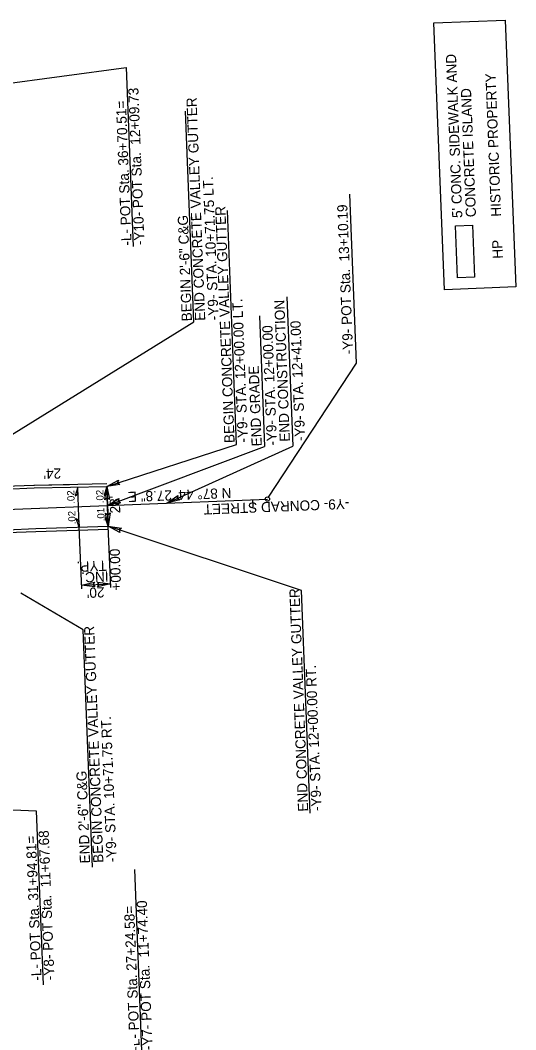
# Model space of a CAD drawing. Extents: x 1627861 to 1629601, y 761281 to 766239.
# Drawn here: x 1628556 to 1628898, y 763512 to 764207 of the extents above; entities that cross this region are included whole.
import ezdxf

# ---------------------------------------------------------------- set-up
doc = ezdxf.new("R2010")
doc.units = 0
for name, color, linetype in [('Cogo Default Point CELL', 7, 'Continuous'), ('Exist Other Culture Sign Leader', 7, 'Continuous'), ('Exist Property Tie Line Text', 7, 'Continuous'), ('Exist Right of Way Line Leader', 7, 'Continuous'), ('Exist Right of Way Monument Text', 7, 'Continuous'), ('Exist Utilities Gas Meter CELL', 7, 'Continuous'), ('Exist Utilities Gas Meter Cogo Number', 7, 'Continuous'), ('Exist Utilities Power UG Cable SUE LOS B Cogo Point CELL', 7, 'Continuous'), ('Exist Utilities Telephone UG Cable SUE LOS B Cogo Point CELL', 7, 'Continuous'), ('Exist Utilities Water UG Line SUE LOS B Cogo Number', 7, 'Continuous'), ('Exist Utilities Water Valve CELL', 7, 'Continuous'), ('Scratch_Level_0', 7, 'Continuous'), ('Typical Terminator CELL', 7, 'Continuous')]:
    doc.layers.add(name, color=color, linetype=linetype)

msp = doc.modelspace()

# ---------------------------------------------------------------- linework, layer by layer
at = {"layer": 'Exist Other Culture Sign Leader'}
msp.add_lwpolyline([(1628848.56, 764021.31), (1628841.32, 764205.02), (1628890.44, 764206.95), (1628897.68, 764023.24)], close=True, dxfattribs=at)
at = {"layer": 'Exist Property Tie Line Text'}
for p, q in [((1628616.55, 763872.84), (1628616.75, 763867.84)), ((1628716.48, 763876.78), (1628716.67, 763871.78))]:
    msp.add_line(p, q, dxfattribs=at)
at = {"layer": 'Exist Right of Way Line Leader'}
for p, q in [((1628407.18, 764144.24), (1628629.31, 764174.43)), ((1628629.31, 764174.43), (1628634.17, 764051.21)), ((1628787.95, 763970.8), (1628783.36, 764087.08)), ((1628727.48, 763878.43), (1628787.95, 763970.8)), ((1628425.93, 763668.97), (1628567.57, 763662.49)), ((1628567.57, 763662.49), (1628572.3, 763542.59)), ((1628640.24, 763497.24), (1628635.31, 763622.14))]:
    msp.add_line(p, q, dxfattribs=at)
msp.add_circle((1628726.66, 763877.18), 1.5, dxfattribs=at)
at = {"layer": 'Exist Right of Way Monument Text'}
for p, q in [((1628566.04, 763884.85), (1628616.04, 763885.81)), ((1628546.06, 763884.07), (1628566.04, 763884.85)), ((1628567.14, 763856.88), (1628617.12, 763858.53)), ((1628547.16, 763856.09), (1628567.14, 763856.88))]:
    msp.add_line(p, q, dxfattribs=at)
at = {"layer": 'Exist Utilities Gas Meter CELL'}
msp.add_line((1628416.71, 763864.95), (1628726.66, 763877.18), dxfattribs=at)
msp.add_line((1628416.71, 763864.95), (1628726.66, 763877.18), dxfattribs=at)
at = {"layer": 'Exist Utilities Gas Meter Cogo Number'}
for points in [[(1628614.85, 763876.75), (1628616.04, 763885.81), (1628618, 763876.83), (1628616.35, 763877.91)], [(1628625.08, 763887.1), (1628616.04, 763885.81), (1628624.16, 763890.11), (1628623.56, 763888.24)], [(1628666.36, 763876.75), (1628657.52, 763874.45), (1628665.11, 763879.64), (1628664.72, 763877.71)], [(1628625.52, 763874.54), (1628616.55, 763872.84), (1628624.47, 763877.51), (1628623.95, 763875.61)], [(1628618.31, 763867.59), (1628617.12, 763858.53), (1628615.16, 763867.51), (1628616.81, 763866.42)], [(1628625.17, 763854.21), (1628617.12, 763858.53), (1628626.21, 763857.19), (1628624.61, 763856.03)], [(1628607.76, 763816.75), (1628598.7, 763817.94), (1628607.68, 763819.9), (1628606.6, 763818.25)], [(1628609.63, 763819.92), (1628618.69, 763818.73), (1628609.71, 763816.77), (1628610.79, 763818.42)]]:
    msp.add_lwpolyline(points, close=True, dxfattribs=at)
at = {"layer": 'Exist Utilities Telephone UG Cable SUE LOS B Cogo Point CELL'}
for p, q in [((1628545.98, 763886.06), (1628565.96, 763886.85)), ((1628566, 763886.85), (1628616, 763887.81)), ((1628547.24, 763854.09), (1628567.22, 763854.88)), ((1628567.21, 763854.88), (1628617.18, 763856.53))]:
    msp.add_line(p, q, dxfattribs=at)
at = {"layer": 'Exist Utilities Water UG Line SUE LOS B Cogo Number'}
for p, q in [((1628597.13, 763857.87), (1628596.04, 763885.43)), ((1628617.12, 763858.53), (1628616.04, 763885.81))]:
    msp.add_line(p, q, dxfattribs=at)
at = {"layer": 'Exist Utilities Water Valve CELL'}
msp.add_lwpolyline([(1628857.58, 764029.59), (1628856.17, 764065.33), (1628867.81, 764065.79), (1628869.22, 764030.05)], close=True, dxfattribs=at)
at = {"layer": 'Scratch_Level_0'}
for p, q in [((1628675.94, 763999.17), (1628670.22, 764144.29)), ((1628705.44, 763914.68), (1628699.08, 764076)), ((1628740.15, 764016.47), (1628744.2, 763913.69)), ((1628721.18, 764003.45), (1628724.73, 763913.41)), ((1628487.81, 763882.77), (1628675.94, 763999.17)), ((1628616.04, 763885.81), (1628705.44, 763914.68)), ((1628616.55, 763872.84), (1628724.73, 763913.41)), ((1628657.52, 763874.45), (1628744.2, 763913.69)), ((1628566.41, 763886.81), (1628590.4, 763887.31)), ((1628616.04, 763885.81), (1628617.12, 763858.53)), ((1628598.8, 763815.44), (1628597.13, 763857.87)), ((1628618.79, 763816.22), (1628617.12, 763858.53)), ((1628750.05, 763814.21), (1628617.12, 763858.53)), ((1628598.7, 763817.94), (1628618.69, 763818.73)), ((1628599.89, 763787.01), (1628557.01, 763812.44)), ((1628756.09, 763660.87), (1628750.05, 763814.21)), ((1628606.33, 763623.75), (1628599.89, 763787.01))]:
    msp.add_line(p, q, dxfattribs=at)
at = {"layer": 'Typical Terminator CELL'}
for points in [[(1628596.04, 763885.43), (1628594.28, 763879.35), (1628596.22, 763880.8)], [(1628616.04, 763885.81), (1628614.28, 763879.73), (1628616.22, 763881.19)], [(1628617.12, 763858.53), (1628614.88, 763864.45), (1628616.94, 763863.15)], [(1628597.13, 763857.87), (1628594.89, 763863.79), (1628596.95, 763862.49)]]:
    msp.add_lwpolyline(points, close=True, dxfattribs=at)

# ---------------------------------------------------------------- texts
at = {"layer": 'Cogo Default Point CELL'}
msp.add_text('N 87%%d 44\' 27.8" E', height=7, rotation=182.25895, dxfattribs=at).set_placement((1628701.73, 763884.89))
at = {"layer": 'Exist Other Culture Sign Leader'}
for s, rotation, p in [("5' CONC. SIDEWALK AND", 92.25819, (1628860.94, 764070.86)), ('HISTORIC PROPERTY', 92.25819, (1628887.6, 764071.76)), ('CONCRETE ISLAND', 92.25819, (1628870.33, 764071.41)), ('HP', 92.25819, (1628888.8, 764042.83)), ('END CONSTRUCTION', 92.25819, (1628742.17, 763916.8)), ('-Y9- STA. 12+00.00', 92.25819, (1628733.31, 763914.02)), ('-Y9- STA. 12+41.00', 92.25819, (1628752.67, 763917.21)), ('END GRADE', 92.25819, (1628722.82, 763913.6)), ('-Y9- CONRAD STREET', 182.25895, (1628782.96, 763877.44))]:
    msp.add_text(s, height=7, rotation=rotation, dxfattribs=at).set_placement(p)
at = {"layer": 'Exist Right of Way Line Leader'}
for s, rotation, p in [('-Y10- POT Sta.  12+09.73', 92.25819, (1628642.07, 764052.18)), ('-L- POT Sta. 36+70.51=', 92.25819, (1628633.21, 764051.83)), ('-Y9- POT Sta.  13+10.19', 92.25895, (1628785.7, 763976.98)), ('-L- POT Sta. 31+94.81=', 92.25819, (1628571.23, 763545.63)), ('-Y8- POT Sta.  11+67.68', 92.25819, (1628580.1, 763545.98)), ('-Y7- POT Sta.  11+74.40', 92.25819, (1628647.71, 763497.7)), ('-L- POT Sta. 27+24.58=', 92.25819, (1628638.84, 763497.35))]:
    msp.add_text(s, height=7, rotation=rotation, dxfattribs=at).set_placement(p)
at = {"layer": 'Exist Utilities Power UG Cable SUE LOS B Cogo Point CELL'}
for s, rotation, p in [('END CONCRETE VALLEY GUTTER', 92.25819, (1628683.91, 764000.08)), ('-Y9- STA. 10+71.75 LT.', 92.25819, (1628693.08, 764000.44)), ('BEGIN CONCRETE VALLEY GUTTER', 92.25819, (1628704.13, 763915.88)), ('BEGIN 2\'-6" C&G', 92.25819, (1628674.74, 763999.71)), ('-Y9- STA. 12+00.00 LT.', 92.25819, (1628713.3, 763916.24)), ("24'", 181.19443, (1628584.58, 763898.33)), ("28'", 92.05859, (1628625.42, 763867.46)), ('+00.00', 92.05859, (1628625.99, 763814.26)), ('TYP.', 182.25895, (1628615.95, 763834.78)), ('INC.', 182.25895, (1628617.16, 763827.39)), ("20'", 182.25895, (1628614.34, 763816.53)), ('END CONCRETE VALLEY GUTTER', 92.25819, (1628754.78, 763662.06)), ('BEGIN CONCRETE VALLEY GUTTER', 92.25819, (1628613.78, 763626.76)), ('-Y9- STA. 12+00.00 RT.', 92.25819, (1628763.95, 763662.42)), ('-Y9- STA. 10+71.75 RT.', 92.25819, (1628622.94, 763627.12)), ('END 2\'-6" C&G', 92.25819, (1628604.61, 763626.39))]:
    msp.add_text(s, height=7, rotation=rotation, dxfattribs=at).set_placement(p)
at = {"layer": 'Exist Utilities Water UG Line SUE LOS B Cogo Number'}
for s, p in [('.02', (1628594.03, 763874)), ('.02', (1628614.03, 763874.38)), ('.02', (1628594.74, 763859.84)), ('.01', (1628614.67, 763861.93))]:
    msp.add_text(s, height=5, rotation=92.25895, dxfattribs=at).set_placement(p)

doc.saveas('drawing.dxf')
